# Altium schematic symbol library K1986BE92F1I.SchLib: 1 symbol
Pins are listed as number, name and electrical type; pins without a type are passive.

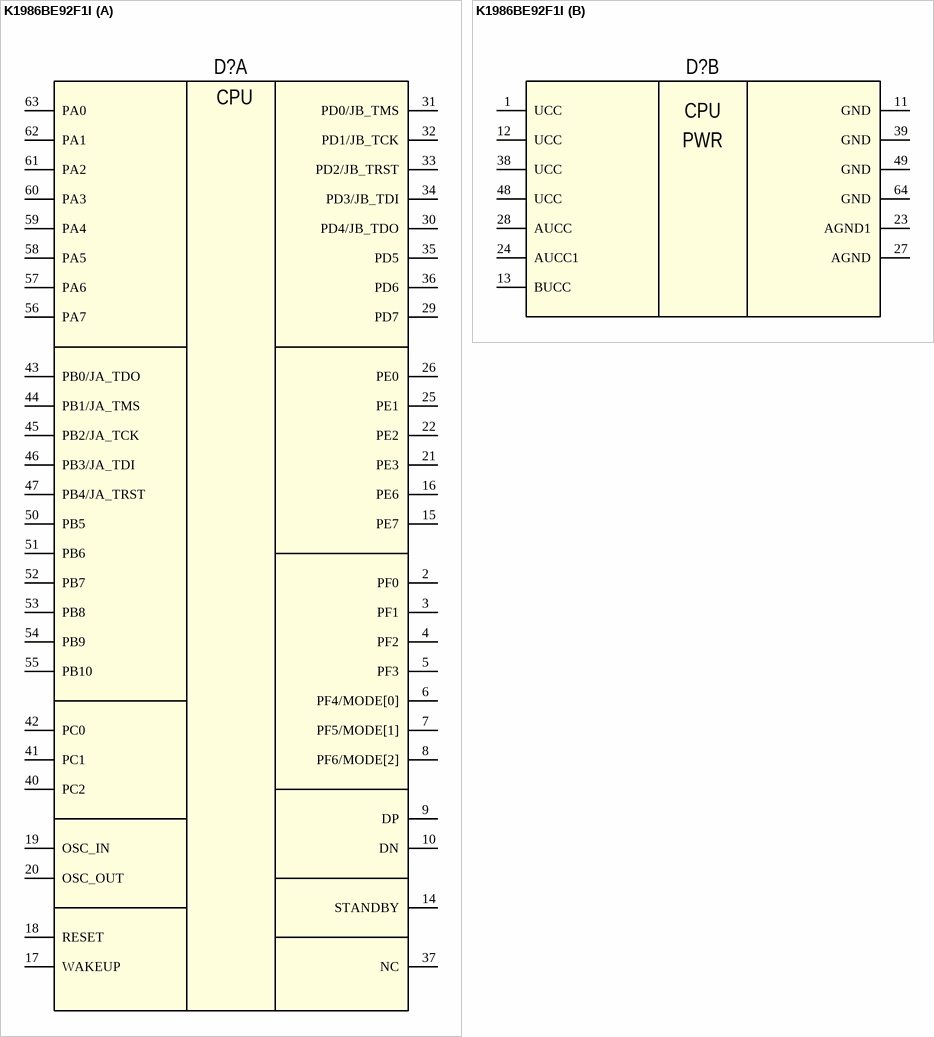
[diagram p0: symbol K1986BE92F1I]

## K1986BE92F1I
designator D?  (value not drawn)
Микросхема 32-разрядного однокристального микро-ЭВМ с памятью Flash-типа; Vendor Code: K1986BE92FI ТСКЯ.431000.001ТУ; Vendor: ООО "Миландр"
footprint QFN 12x12x1,6(0,5)
part A pins: 2 PF0, 3 PF1, 4 PF2, 5 PF3, 6 PF4/MODE[0], 7 PF5/MODE[1], 8 PF6/MODE[2], 9 DP, 10 DN, 14 STANDBY, 15 PE7, 16 PE6, 17 WAKEUP, 18 RESET, 19 OSC_IN, 20 OSC_OUT, 21 PE3, 22 PE2, 25 PE1, 26 PE0, 29 PD7, 30 PD4/JB_TDO, 31 PD0/JB_TMS, 32 PD1/JB_TCK, 33 PD2/JB_TRST, 34 PD3/JB_TDI, 35 PD5, 36 PD6, 37 NC, 40 PC2, 41 PC1, 42 PC0, 43 PB0/JA_TDO, 44 PB1/JA_TMS, 45 PB2/JA_TCK, 46 PB3/JA_TDI, 47 PB4/JA_TRST, 50 PB5, 51 PB6, 52 PB7, 53 PB8, 54 PB9, 55 PB10, 56 PA7, 57 PA6, 58 PA5, 59 PA4, 60 PA3, 61 PA2, 62 PA1, 63 PA0
part B pins: 1 UCC, 11 GND, 12 UCC, 13 BUCC, 23 AGND1, 24 AUCC1, 27 AGND, 28 AUCC, 38 UCC, 39 GND, 48 UCC, 49 GND, 64 GND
